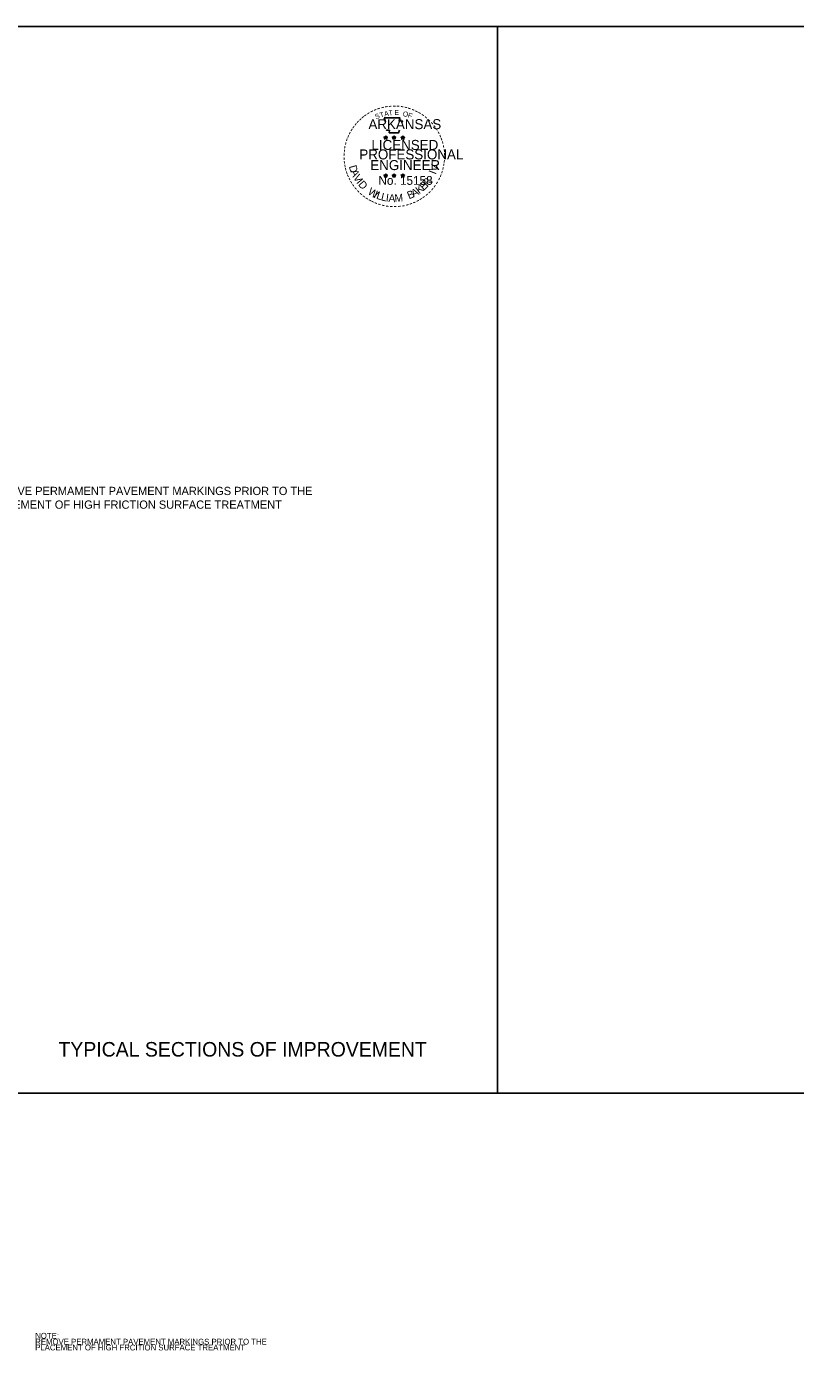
# Model space of a CAD drawing. Extents: x 96 to 721, y -177 to -41.
# Drawn here: x 296.8 to 376.2, y -177.1 to -40.6 of the extents above; entities that cross this region are included whole.
import ezdxf

# ---------------------------------------------------------------- set-up
doc = ezdxf.new("R2010")
doc.units = 0
for name, color, linetype in [('R_Border', 7, 'Continuous'), ('R_Border Notes', 7, 'Continuous'), ('R_Border PE', 7, 'Continuous'), ('SHET_Border-Lines', 7, 'Continuous'), ('SHET_Stamp-Prelim', 7, 'Continuous')]:
    doc.layers.add(name, color=color, linetype=linetype)

msp = doc.modelspace()

# ---------------------------------------------------------------- linework, layer by layer
at = {"layer": 'R_Border'}
for points in [[(175.41, -40.58), (345.41, -40.58), (345.41, -150.58), (175.41, -150.58)], [(175.41, -40.58), (175.41, -150.58), (345.41, -150.58), (345.41, -40.58)], [(345.41, -40.58), (515.41, -40.58), (515.41, -150.58), (345.41, -150.58)], [(345.41, -40.58), (345.41, -150.58), (515.41, -150.58), (515.41, -40.58)]]:
    msp.add_lwpolyline(points, close=True, dxfattribs=at)
at = {"layer": 'R_Border Notes'}
msp.add_lwpolyline([(175.41, -150.58), (345.41, -150.58), (345.41, -40.58), (175.41, -40.58)], close=True, dxfattribs=at)
at = {"layer": 'R_Border PE'}
for p, q in [((333.87, -51.86), (333.85, -51.99)), ((333.87, -52.05), (333.87, -51.86)), ((333.87, -51.86), (333.9, -51.99)), ((334.73, -51.86), (334.71, -51.99)), ((334.73, -52.05), (334.73, -51.86)), ((334.73, -51.86), (334.76, -51.99)), ((335.64, -51.87), (335.62, -52)), ((335.64, -52.05), (335.64, -51.87)), ((335.64, -51.87), (335.67, -51.99)), ((333.69, -51.99), (333.87, -52.05)), ((333.69, -51.99), (333.82, -52.01)), ((333.69, -51.99), (333.82, -52.05)), ((333.76, -52.2), (333.87, -52.05)), ((333.76, -52.2), (333.83, -52.07)), ((333.76, -52.2), (333.87, -52.09)), ((334.05, -51.99), (333.87, -52.05)), ((333.98, -52.2), (333.87, -52.05)), ((333.98, -52.2), (333.87, -52.09)), ((334.05, -51.99), (333.91, -52.02)), ((333.98, -52.2), (333.91, -52.05)), ((334.05, -51.99), (333.95, -52.04)), ((334.55, -51.99), (334.73, -52.05)), ((334.55, -51.99), (334.69, -52.01)), ((334.55, -51.99), (334.68, -52.05)), ((334.62, -52.2), (334.73, -52.05)), ((334.62, -52.2), (334.69, -52.07)), ((334.62, -52.2), (334.73, -52.09)), ((334.91, -51.99), (334.73, -52.05)), ((334.84, -52.2), (334.73, -52.05)), ((334.84, -52.2), (334.73, -52.09)), ((334.91, -51.99), (334.77, -52.02)), ((334.84, -52.2), (334.77, -52.05)), ((334.91, -51.99), (334.81, -52.04)), ((335.46, -52), (335.64, -52.05)), ((335.46, -52), (335.6, -52.02)), ((335.46, -52), (335.59, -52.06)), ((335.53, -52.21), (335.64, -52.05)), ((335.53, -52.21), (335.6, -52.08)), ((335.53, -52.21), (335.64, -52.09)), ((335.82, -52), (335.64, -52.05)), ((335.75, -52.21), (335.64, -52.05)), ((335.75, -52.21), (335.64, -52.1)), ((335.82, -52), (335.68, -52.02)), ((335.75, -52.21), (335.68, -52.06)), ((335.82, -52), (335.72, -52.05)), ((333.69, -55.9), (333.87, -55.95)), ((333.69, -55.9), (333.82, -55.92)), ((333.69, -55.9), (333.81, -55.96)), ((333.76, -56.11), (333.87, -55.95)), ((333.87, -55.76), (333.85, -55.89)), ((333.87, -55.95), (333.87, -55.76)), ((333.87, -55.76), (333.9, -55.89)), ((334.05, -55.9), (333.87, -55.95)), ((333.98, -56.11), (333.87, -55.95)), ((334.05, -55.9), (333.9, -55.92)), ((333.98, -56.11), (333.91, -55.96)), ((334.05, -55.9), (333.95, -55.95)), ((334.55, -55.9), (334.73, -55.95)), ((334.55, -55.9), (334.68, -55.92)), ((334.55, -55.9), (334.67, -55.96)), ((334.62, -56.11), (334.73, -55.95)), ((334.73, -55.76), (334.71, -55.89)), ((334.73, -55.95), (334.73, -55.76)), ((334.73, -55.76), (334.76, -55.89)), ((334.91, -55.9), (334.73, -55.95)), ((334.84, -56.11), (334.73, -55.95)), ((334.91, -55.9), (334.76, -55.92)), ((334.84, -56.11), (334.77, -55.96)), ((334.91, -55.9), (334.81, -55.95)), ((335.46, -55.9), (335.64, -55.96)), ((335.46, -55.9), (335.59, -55.92)), ((335.46, -55.9), (335.59, -55.96)), ((335.53, -56.11), (335.64, -55.96)), ((335.64, -55.77), (335.62, -55.9)), ((335.64, -55.96), (335.64, -55.77)), ((335.64, -55.77), (335.67, -55.9)), ((335.82, -55.9), (335.64, -55.96)), ((335.75, -56.11), (335.64, -55.96)), ((335.82, -55.9), (335.67, -55.93)), ((335.75, -56.11), (335.68, -55.96)), ((335.82, -55.9), (335.72, -55.95)), ((333.76, -56.11), (333.83, -55.98)), ((333.76, -56.11), (333.87, -55.99)), ((333.98, -56.11), (333.87, -56)), ((334.62, -56.11), (334.69, -55.98)), ((334.62, -56.11), (334.73, -55.99)), ((334.84, -56.11), (334.73, -56)), ((335.53, -56.11), (335.6, -55.98)), ((335.53, -56.11), (335.64, -56)), ((335.75, -56.11), (335.64, -56))]:
    msp.add_line(p, q, dxfattribs=at)
for points in [[(333.72, -49.99), (333.85, -50.42)], [(335.53, -50.47), (335.6, -50.32), (335.25, -50.33), (335.32, -49.99), (333.72, -49.99)], [(333.87, -51.86), (333.98, -52.2), (333.69, -51.99), (334.05, -51.99), (333.76, -52.2), (333.87, -51.86)], [(333.97, -51.24), (333.97, -51.28), (334.26, -51.29), (334.23, -51.54), (335.2, -51.54), (335.3, -51.26)], [(334.73, -51.86), (334.84, -52.2), (334.55, -51.99), (334.91, -51.99), (334.62, -52.2), (334.73, -51.86)], [(335.64, -51.87), (335.75, -52.21), (335.46, -52), (335.82, -52), (335.53, -52.21), (335.64, -51.87)], [(333.87, -55.76), (333.98, -56.11), (333.69, -55.9), (334.05, -55.9), (333.76, -56.11), (333.87, -55.76)], [(334.73, -55.76), (334.84, -56.11), (334.55, -55.9), (334.91, -55.9), (334.62, -56.11), (334.73, -55.76)], [(335.64, -55.77), (335.75, -56.11), (335.46, -55.9), (335.82, -55.9), (335.53, -56.11), (335.64, -55.77)]]:
    msp.add_lwpolyline(points, dxfattribs=at)
for centre, radius in [((333.87, -52.05), 0.0888), ((333.87, -52.05), 0.0745), ((333.87, -52.05), 0.0597), ((333.87, -52.05), 0.0511), ((333.87, -52.05), 0.0385), ((333.87, -52.05), 0.0255), ((333.87, -52.05), 0.0153), ((334.73, -52.05), 0.0888), ((334.73, -52.05), 0.0745), ((334.73, -52.05), 0.0597), ((334.73, -52.05), 0.0511), ((334.73, -52.05), 0.0385), ((334.73, -52.05), 0.0255), ((334.73, -52.05), 0.0153), ((335.64, -52.05), 0.0888), ((335.64, -52.05), 0.0745), ((335.64, -52.05), 0.0597), ((335.64, -52.05), 0.0511), ((335.64, -52.05), 0.0385), ((335.64, -52.05), 0.0255), ((335.64, -52.05), 0.0153), ((333.87, -55.95), 0.0888), ((333.87, -55.95), 0.0745), ((333.87, -55.95), 0.0597), ((333.87, -55.95), 0.0511), ((333.87, -55.95), 0.0385), ((333.87, -55.95), 0.0255), ((333.87, -55.95), 0.0153), ((334.73, -55.95), 0.0888), ((334.73, -55.95), 0.0745), ((334.73, -55.95), 0.0597), ((334.73, -55.95), 0.0511), ((334.73, -55.95), 0.0385), ((334.73, -55.95), 0.0255), ((334.73, -55.95), 0.0153), ((335.64, -55.96), 0.0888), ((335.64, -55.96), 0.0745), ((335.64, -55.96), 0.0597), ((335.64, -55.96), 0.0511), ((335.64, -55.96), 0.0385), ((335.64, -55.96), 0.0255), ((335.64, -55.96), 0.0153)]:
    msp.add_circle(centre, radius, dxfattribs=at)

# ---------------------------------------------------------------- texts
for s, height, rotation, p in [('-', 0.825, 24.3072, (332.74, -49.55)), ('-', 0.825, 19.1761, (333.07, -49.41)), ('-', 0.825, 13.6302, (333.46, -49.29)), ('-', 0.825, 10.2193, (333.81, -49.2)), ('-', 0.825, 5.8968, (334.18, -49.15)), ('-', 0.825, 0.1862, (334.58, -49.11)), ('-', 0.825, 357.743, (334.95, -49.11)), ('-', 0.825, 352.1617, (335.34, -49.14)), ('-', 0.825, 347.2049, (335.71, -49.2)), ('-', 0.825, 342.3362, (336.03, -49.28)), ('-', 0.825, 337.8551, (336.41, -49.4)), ('-', 0.825, 48.4231, (331.11, -50.76)), ('-', 0.825, 42.9622, (331.34, -50.52)), ('-', 0.825, 38.9507, (331.56, -50.3)), ('-', 0.825, 36.2317, (331.81, -50.11)), ('-', 0.825, 34.0636, (332.11, -49.9)), ('-', 0.825, 28.7918, (332.42, -49.71)), ('S', 0.516, 21.594, (332.87, -50.16)), ('T', 0.516, 16.4036, (333.34, -49.99)), ('A', 0.516, 11.2132, (333.76, -49.86)), ('T', 0.516, 6.0228, (334.2, -49.77)), ('E', 0.516, 0.8323, (334.77, -49.71)), ('O', 0.516, 350.4515, (335.6, -49.82)), ('F', 0.516, 340.0707, (336.09, -49.94)), ('-', 0.825, 334.1211, (336.74, -49.54)), ('-', 0.825, 329.6409, (337.04, -49.68)), ('-', 0.825, 325.8627, (337.37, -49.87)), ('-', 0.825, 320.5297, (337.68, -50.09)), ('-', 0.825, 315.5786, (337.99, -50.34)), ('-', 0.825, 309.8797, (338.29, -50.62)), ('-', 0.825, 67.7743, (330.23, -52.21)), ('-', 0.825, 62.8713, (330.36, -51.89)), ('-', 0.825, 58.0706, (330.52, -51.58)), ('-', 0.825, 54.2325, (330.69, -51.31)), ('-', 0.825, 50.6142, (330.9, -51.01)), ('-', 0.825, 306.6522, (338.56, -50.93)), ('-', 0.722, 303.6753, (338.81, -51.23)), ('-', 0.825, 299.6684, (338.97, -51.54)), ('-', 0.825, 294.6628, (339.14, -51.86)), ('-', 0.825, 81.2013, (329.94, -53.27)), ('-', 0.825, 75.461, (330.01, -52.9)), ('-', 0.825, 72.3945, (330.11, -52.53)), ('-', 0.825, 290.5728, (339.27, -52.15)), ('-', 0.825, 285.1233, (339.39, -52.45)), ('-', 0.825, 280.5493, (339.49, -52.83)), ('-', 0.825, 276.5962, (339.58, -53.23)), ('-', 0.825, 94.1959, (329.91, -54.36)), ('-', 0.825, 89.0622, (329.89, -53.99)), ('-', 0.825, 98.9479, (329.95, -54.71)), ('-', 0.825, 85.1863, (329.91, -53.63)), ('-', 0.825, 263.5172, (339.62, -54.27)), ('-', 0.825, 274.3301, (339.61, -53.6)), ('-', 0.825, 269.9407, (339.63, -53.93)), ('-', 0.825, 101.7149, (330.02, -55.08)), ('-', 0.825, 105.4578, (330.1, -55.39)), ('-', 0.825, 109.0874, (330.21, -55.72)), ('-', 0.825, 114.0643, (330.34, -56.02)), ('D', 0.794, 286.2848, (330.06, -55.01)), ('A', 0.794, 292.7835, (330.21, -55.53)), ('V', 0.794, 300.7936, (330.48, -56.14)), ('I', 0.794, 69.0301, (339.02, -55.89)), ('V', 0.794, 72.6573, (339.13, -55.61)), ('-', 0.825, 247.8887, (339.32, -55.68)), ('-', 0.825, 252.8681, (339.43, -55.33)), ('-', 0.825, 255.7626, (339.52, -54.96)), ('-', 0.825, 260.9953, (339.58, -54.61)), ('-', 0.825, 115.7289, (330.5, -56.34)), ('-', 0.825, 120.4471, (330.68, -56.64)), ('-', 0.825, 125.8934, (330.89, -56.93)), ('-', 0.825, 130.7181, (331.13, -57.22)), ('I', 0.794, 308.3502, (330.8, -56.67)), ('D', 0.794, 311.9774, (330.98, -56.91)), ('W', 0.794, 328.0731, (331.95, -57.82)), ('A', 0.794, 28.9042, (336.75, -58.22)), ('K', 0.794, 36.9143, (337.32, -57.89)), ('E', 0.794, 44.0175, (337.79, -57.54)), ('R', 0.794, 50.3651, (338.17, -57.17)), (',', 0.794, 57.4684, (338.54, -56.72)), ('-', 0.825, 231.2538, (338.55, -57.02)), ('-', 0.825, 233.8452, (338.77, -56.73)), ('-', 0.825, 239.0712, (338.98, -56.39)), ('-', 0.825, 244.6197, (339.18, -56)), ('-', 0.825, 134.2238, (331.4, -57.5)), ('-', 0.825, 138.9338, (331.67, -57.74)), ('-', 0.825, 144.6463, (331.95, -57.95)), ('-', 0.825, 148.0898, (332.24, -58.14)), ('-', 0.825, 151.5704, (332.54, -58.31)), ('-', 0.825, 154.6002, (332.81, -58.43)), ('I', 0.794, 336.6877, (332.57, -58.19)), ('-', 0.825, 158.5612, (333.13, -58.56)), ('L', 0.794, 340.3149, (332.84, -58.31)), ('L', 0.794, 346.6625, (333.33, -58.49)), ('I', 0.794, 353.0101, (333.85, -58.61)), ('A', 0.794, 356.6373, (334.14, -58.66)), ('M', 0.794, 4.6473, (334.81, -58.69)), ('B', 0.794, 22.8589, (336.28, -58.41)), ('-', 0.825, 204.2516, (336.86, -58.36)), ('-', 0.825, 207.3568, (337.19, -58.19)), ('-', 0.825, 212.2491, (337.47, -58.01)), ('-', 0.825, 215.7363, (337.75, -57.81)), ('-', 0.825, 221.0851, (338.03, -57.57)), ('-', 0.825, 225.7653, (338.3, -57.31)), ('-', 0.825, 162.7983, (333.49, -58.67)), ('-', 0.825, 167.5555, (333.86, -58.76)), ('-', 0.825, 173.1155, (334.25, -58.82)), ('-', 0.825, 176.5183, (334.64, -58.84)), ('-', 0.825, 181.5918, (335.02, -58.83)), ('-', 0.825, 185.8167, (335.44, -58.79)), ('-', 0.825, 191.2858, (335.82, -58.73)), ('-', 0.825, 195.4743, (336.2, -58.62)), ('-', 0.825, 199.4643, (336.54, -58.5))]:
    msp.add_text(s, height=height, rotation=rotation, dxfattribs=at).set_placement(p)
for s, height, p in [('ARKANSAS', 1.031, (332.09, -51.17)), ('PROFESSIONAL', 1.0312, (331.15, -54.29)), ('LICENSED', 1.031, (332.4, -53.31)), ('ENGINEER', 1.031, (332.28, -55.39)), ('No. 15158', 0.906, (333.12, -56.91)), ('AAMU', 0.0000103, (334.7, -58.69))]:
    msp.add_text(s, height=height, dxfattribs=at).set_placement(p)
at = {"layer": 'SHET_Border-Lines'}
for s, height, p in [('REMOVE PERMAMENT PAVEMENT MARKINGS PRIOR TO THE ', 0.85, (292.47, -88.9)), ('PLACEMENT OF HIGH FRICTION SURFACE TREATMENT', 0.85, (292.47, -90.31)), ('NOTE:', 0.6, (297.71, -175.89)), ('REMOVE PERMAMENT PAVEMENT MARKINGS PRIOR TO THE ', 0.6, (297.71, -176.5)), ('PLACEMENT OF HIGH FRCITION SURFACE TREATMENT', 0.6, (297.71, -177.1))]:
    msp.add_text(s, height=height, dxfattribs=at).set_placement(p)
at = {"layer": 'SHET_Stamp-Prelim'}
msp.add_text('TYPICAL SECTIONS OF IMPROVEMENT', height=1.5, dxfattribs=at).set_placement((300.11, -146.8))

doc.saveas('drawing.dxf')
